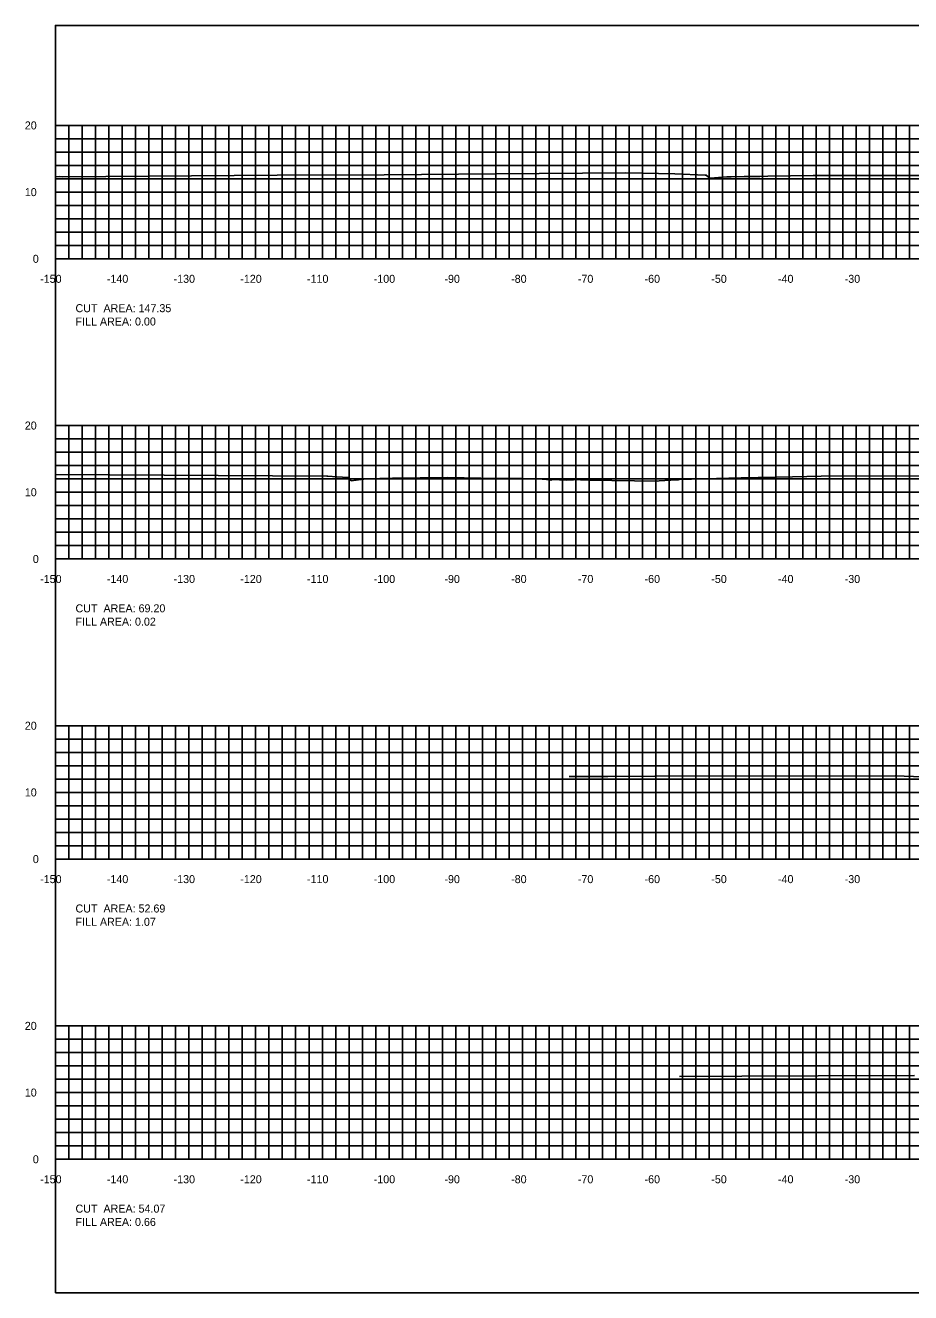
# Model space of a CAD drawing. Extents: x 1800674 to 1802785, y 250079 to 250269.
# Drawn here: x 1802136.5 to 1802269.2, y 250079.4 to 250269.4 of the extents above; entities that cross this region are included whole.
import ezdxf

# ---------------------------------------------------------------- set-up
doc = ezdxf.new("R2010")
doc.units = 0
for name, color, linetype in [('10', 7, 'Continuous'), ('31', 7, 'Continuous'), ('60', 7, 'Continuous'), ('ANNO-TXT', 7, 'Continuous'), ('Level 62', 7, 'Continuous'), ('M-ROADS', 7, 'Continuous')]:
    doc.layers.add(name, color=color, linetype=linetype)

msp = doc.modelspace()

# ---------------------------------------------------------------- linework, layer by layer
msp.add_lwpolyline([(1802141, 250079.43), (1802441, 250079.43), (1802441, 250269.43), (1802141, 250269.43)], close=True)
at = {"layer": '60'}
for p, q in [((1802140.94, 250254.43), (1802141, 250254.43)), ((1802141, 250234.43), (1802141, 250254.43)), ((1802140.94, 250244.43), (1802141, 250244.43)), ((1802140.94, 250234.43), (1802141, 250234.43)), ((1802141, 250234.43), (1802441, 250234.43)), ((1802141, 250234.37), (1802141, 250234.43)), ((1802151, 250234.37), (1802151, 250234.43)), ((1802161, 250234.37), (1802161, 250234.43)), ((1802171, 250234.37), (1802171, 250234.43)), ((1802181, 250234.37), (1802181, 250234.43)), ((1802191, 250234.37), (1802191, 250234.43)), ((1802201, 250234.37), (1802201, 250234.43)), ((1802211, 250234.37), (1802211, 250234.43)), ((1802221, 250234.37), (1802221, 250234.43)), ((1802231, 250234.37), (1802231, 250234.43)), ((1802241, 250234.37), (1802241, 250234.43)), ((1802251, 250234.37), (1802251, 250234.43)), ((1802261, 250234.37), (1802261, 250234.43)), ((1802140.94, 250209.43), (1802141, 250209.43)), ((1802141, 250189.43), (1802141, 250209.43)), ((1802140.94, 250199.43), (1802141, 250199.43)), ((1802140.94, 250189.43), (1802141, 250189.43)), ((1802141, 250189.43), (1802441, 250189.43)), ((1802141, 250189.37), (1802141, 250189.43)), ((1802151, 250189.37), (1802151, 250189.43)), ((1802161, 250189.37), (1802161, 250189.43)), ((1802171, 250189.37), (1802171, 250189.43)), ((1802181, 250189.37), (1802181, 250189.43)), ((1802191, 250189.37), (1802191, 250189.43)), ((1802201, 250189.37), (1802201, 250189.43)), ((1802211, 250189.37), (1802211, 250189.43)), ((1802221, 250189.37), (1802221, 250189.43)), ((1802231, 250189.37), (1802231, 250189.43)), ((1802241, 250189.37), (1802241, 250189.43)), ((1802251, 250189.37), (1802251, 250189.43)), ((1802261, 250189.37), (1802261, 250189.43)), ((1802140.94, 250164.43), (1802141, 250164.43)), ((1802141, 250144.43), (1802141, 250164.43)), ((1802140.94, 250154.43), (1802141, 250154.43)), ((1802140.94, 250144.43), (1802141, 250144.43)), ((1802141, 250144.43), (1802441, 250144.43)), ((1802141, 250144.37), (1802141, 250144.43)), ((1802151, 250144.37), (1802151, 250144.43)), ((1802161, 250144.37), (1802161, 250144.43)), ((1802171, 250144.37), (1802171, 250144.43)), ((1802181, 250144.37), (1802181, 250144.43)), ((1802191, 250144.37), (1802191, 250144.43)), ((1802201, 250144.37), (1802201, 250144.43)), ((1802211, 250144.37), (1802211, 250144.43)), ((1802221, 250144.37), (1802221, 250144.43)), ((1802231, 250144.37), (1802231, 250144.43)), ((1802241, 250144.37), (1802241, 250144.43)), ((1802251, 250144.37), (1802251, 250144.43)), ((1802261, 250144.37), (1802261, 250144.43)), ((1802140.94, 250119.43), (1802141, 250119.43)), ((1802141, 250099.43), (1802141, 250119.43)), ((1802140.94, 250109.43), (1802141, 250109.43)), ((1802140.94, 250099.43), (1802141, 250099.43)), ((1802141, 250099.43), (1802441, 250099.43)), ((1802141, 250099.37), (1802141, 250099.43)), ((1802151, 250099.37), (1802151, 250099.43)), ((1802161, 250099.37), (1802161, 250099.43)), ((1802171, 250099.37), (1802171, 250099.43)), ((1802181, 250099.37), (1802181, 250099.43)), ((1802191, 250099.37), (1802191, 250099.43)), ((1802201, 250099.37), (1802201, 250099.43)), ((1802211, 250099.37), (1802211, 250099.43)), ((1802221, 250099.37), (1802221, 250099.43)), ((1802231, 250099.37), (1802231, 250099.43)), ((1802241, 250099.37), (1802241, 250099.43)), ((1802251, 250099.37), (1802251, 250099.43)), ((1802261, 250099.37), (1802261, 250099.43))]:
    msp.add_line(p, q, dxfattribs=at)
at = {"layer": 'Level 62'}
for p, q in [((1802141, 250254.43), (1802441, 250254.43)), ((1802141, 250234.43), (1802141, 250254.43)), ((1802143, 250234.43), (1802143, 250254.43)), ((1802145, 250234.43), (1802145, 250254.43)), ((1802147, 250234.43), (1802147, 250254.43)), ((1802149, 250234.43), (1802149, 250254.43)), ((1802151, 250234.43), (1802151, 250254.43)), ((1802153, 250234.43), (1802153, 250254.43)), ((1802155, 250234.43), (1802155, 250254.43)), ((1802157, 250234.43), (1802157, 250254.43)), ((1802159, 250234.43), (1802159, 250254.43)), ((1802161, 250234.43), (1802161, 250254.43)), ((1802163, 250234.43), (1802163, 250254.43)), ((1802165, 250234.43), (1802165, 250254.43)), ((1802167, 250234.43), (1802167, 250254.43)), ((1802169, 250234.43), (1802169, 250254.43)), ((1802171, 250234.43), (1802171, 250254.43)), ((1802173, 250234.43), (1802173, 250254.43)), ((1802175, 250234.43), (1802175, 250254.43)), ((1802177, 250234.43), (1802177, 250254.43)), ((1802179, 250234.43), (1802179, 250254.43)), ((1802181, 250234.43), (1802181, 250254.43)), ((1802183, 250234.43), (1802183, 250254.43)), ((1802185, 250234.43), (1802185, 250254.43)), ((1802187, 250234.43), (1802187, 250254.43)), ((1802189, 250234.43), (1802189, 250254.43)), ((1802191, 250234.43), (1802191, 250254.43)), ((1802193, 250234.43), (1802193, 250254.43)), ((1802195, 250234.43), (1802195, 250254.43)), ((1802197, 250234.43), (1802197, 250254.43)), ((1802199, 250234.43), (1802199, 250254.43)), ((1802201, 250234.43), (1802201, 250254.43)), ((1802203, 250234.43), (1802203, 250254.43)), ((1802205, 250234.43), (1802205, 250254.43)), ((1802207, 250234.43), (1802207, 250254.43)), ((1802209, 250234.43), (1802209, 250254.43)), ((1802211, 250234.43), (1802211, 250254.43)), ((1802213, 250234.43), (1802213, 250254.43)), ((1802215, 250234.43), (1802215, 250254.43)), ((1802217, 250234.43), (1802217, 250254.43)), ((1802219, 250234.43), (1802219, 250254.43)), ((1802221, 250234.43), (1802221, 250254.43)), ((1802223, 250234.43), (1802223, 250254.43)), ((1802225, 250234.43), (1802225, 250254.43)), ((1802227, 250234.43), (1802227, 250254.43)), ((1802229, 250234.43), (1802229, 250254.43)), ((1802231, 250234.43), (1802231, 250254.43)), ((1802233, 250234.43), (1802233, 250254.43)), ((1802235, 250234.43), (1802235, 250254.43)), ((1802237, 250234.43), (1802237, 250254.43)), ((1802239, 250234.43), (1802239, 250254.43)), ((1802241, 250234.43), (1802241, 250254.43)), ((1802243, 250234.43), (1802243, 250254.43)), ((1802245, 250234.43), (1802245, 250254.43)), ((1802247, 250234.43), (1802247, 250254.43)), ((1802249, 250234.43), (1802249, 250254.43)), ((1802251, 250234.43), (1802251, 250254.43)), ((1802253, 250234.43), (1802253, 250254.43)), ((1802255, 250234.43), (1802255, 250254.43)), ((1802257, 250234.43), (1802257, 250254.43)), ((1802259, 250234.43), (1802259, 250254.43)), ((1802261, 250234.43), (1802261, 250254.43)), ((1802263, 250234.43), (1802263, 250254.43)), ((1802265, 250234.43), (1802265, 250254.43)), ((1802267, 250234.43), (1802267, 250254.43)), ((1802269, 250234.43), (1802269, 250254.43)), ((1802141, 250252.43), (1802441, 250252.43)), ((1802141, 250250.43), (1802441, 250250.43)), ((1802141, 250248.43), (1802441, 250248.43)), ((1802141, 250246.43), (1802441, 250246.43)), ((1802141, 250244.43), (1802441, 250244.43)), ((1802141, 250242.43), (1802441, 250242.43)), ((1802141, 250240.43), (1802441, 250240.43)), ((1802141, 250238.43), (1802441, 250238.43)), ((1802141, 250236.43), (1802441, 250236.43)), ((1802141, 250234.43), (1802441, 250234.43)), ((1802141, 250209.43), (1802441, 250209.43)), ((1802141, 250189.43), (1802141, 250209.43)), ((1802143, 250189.43), (1802143, 250209.43)), ((1802145, 250189.43), (1802145, 250209.43)), ((1802147, 250189.43), (1802147, 250209.43)), ((1802149, 250189.43), (1802149, 250209.43)), ((1802151, 250189.43), (1802151, 250209.43)), ((1802153, 250189.43), (1802153, 250209.43)), ((1802155, 250189.43), (1802155, 250209.43)), ((1802157, 250189.43), (1802157, 250209.43)), ((1802159, 250189.43), (1802159, 250209.43)), ((1802161, 250189.43), (1802161, 250209.43)), ((1802163, 250189.43), (1802163, 250209.43)), ((1802165, 250189.43), (1802165, 250209.43)), ((1802167, 250189.43), (1802167, 250209.43)), ((1802169, 250189.43), (1802169, 250209.43)), ((1802171, 250189.43), (1802171, 250209.43)), ((1802173, 250189.43), (1802173, 250209.43)), ((1802175, 250189.43), (1802175, 250209.43)), ((1802177, 250189.43), (1802177, 250209.43)), ((1802179, 250189.43), (1802179, 250209.43)), ((1802181, 250189.43), (1802181, 250209.43)), ((1802183, 250189.43), (1802183, 250209.43)), ((1802185, 250189.43), (1802185, 250209.43)), ((1802187, 250189.43), (1802187, 250209.43)), ((1802189, 250189.43), (1802189, 250209.43)), ((1802191, 250189.43), (1802191, 250209.43)), ((1802193, 250189.43), (1802193, 250209.43)), ((1802195, 250189.43), (1802195, 250209.43)), ((1802197, 250189.43), (1802197, 250209.43)), ((1802199, 250189.43), (1802199, 250209.43)), ((1802201, 250189.43), (1802201, 250209.43)), ((1802203, 250189.43), (1802203, 250209.43)), ((1802205, 250189.43), (1802205, 250209.43)), ((1802207, 250189.43), (1802207, 250209.43)), ((1802209, 250189.43), (1802209, 250209.43)), ((1802211, 250189.43), (1802211, 250209.43)), ((1802213, 250189.43), (1802213, 250209.43)), ((1802215, 250189.43), (1802215, 250209.43)), ((1802217, 250189.43), (1802217, 250209.43)), ((1802219, 250189.43), (1802219, 250209.43)), ((1802221, 250189.43), (1802221, 250209.43)), ((1802223, 250189.43), (1802223, 250209.43)), ((1802225, 250189.43), (1802225, 250209.43)), ((1802227, 250189.43), (1802227, 250209.43)), ((1802229, 250189.43), (1802229, 250209.43)), ((1802231, 250189.43), (1802231, 250209.43)), ((1802233, 250189.43), (1802233, 250209.43)), ((1802235, 250189.43), (1802235, 250209.43)), ((1802237, 250189.43), (1802237, 250209.43)), ((1802239, 250189.43), (1802239, 250209.43)), ((1802241, 250189.43), (1802241, 250209.43)), ((1802243, 250189.43), (1802243, 250209.43)), ((1802245, 250189.43), (1802245, 250209.43)), ((1802247, 250189.43), (1802247, 250209.43)), ((1802249, 250189.43), (1802249, 250209.43)), ((1802251, 250189.43), (1802251, 250209.43)), ((1802253, 250189.43), (1802253, 250209.43)), ((1802255, 250189.43), (1802255, 250209.43)), ((1802257, 250189.43), (1802257, 250209.43)), ((1802259, 250189.43), (1802259, 250209.43)), ((1802261, 250189.43), (1802261, 250209.43)), ((1802263, 250189.43), (1802263, 250209.43)), ((1802265, 250189.43), (1802265, 250209.43)), ((1802267, 250189.43), (1802267, 250209.43)), ((1802269, 250189.43), (1802269, 250209.43)), ((1802141, 250207.43), (1802441, 250207.43)), ((1802141, 250205.43), (1802441, 250205.43)), ((1802141, 250203.43), (1802441, 250203.43)), ((1802141, 250201.43), (1802441, 250201.43)), ((1802141, 250199.43), (1802441, 250199.43)), ((1802141, 250197.43), (1802441, 250197.43)), ((1802141, 250195.43), (1802441, 250195.43)), ((1802141, 250193.43), (1802441, 250193.43)), ((1802141, 250191.43), (1802441, 250191.43)), ((1802141, 250189.43), (1802441, 250189.43)), ((1802141, 250164.43), (1802441, 250164.43)), ((1802141, 250144.43), (1802141, 250164.43)), ((1802143, 250144.43), (1802143, 250164.43)), ((1802145, 250144.43), (1802145, 250164.43)), ((1802147, 250144.43), (1802147, 250164.43)), ((1802149, 250144.43), (1802149, 250164.43)), ((1802151, 250144.43), (1802151, 250164.43)), ((1802153, 250144.43), (1802153, 250164.43)), ((1802155, 250144.43), (1802155, 250164.43)), ((1802157, 250144.43), (1802157, 250164.43)), ((1802159, 250144.43), (1802159, 250164.43)), ((1802161, 250144.43), (1802161, 250164.43)), ((1802163, 250144.43), (1802163, 250164.43)), ((1802165, 250144.43), (1802165, 250164.43)), ((1802167, 250144.43), (1802167, 250164.43)), ((1802169, 250144.43), (1802169, 250164.43)), ((1802171, 250144.43), (1802171, 250164.43)), ((1802173, 250144.43), (1802173, 250164.43)), ((1802175, 250144.43), (1802175, 250164.43)), ((1802177, 250144.43), (1802177, 250164.43)), ((1802179, 250144.43), (1802179, 250164.43)), ((1802181, 250144.43), (1802181, 250164.43)), ((1802183, 250144.43), (1802183, 250164.43)), ((1802185, 250144.43), (1802185, 250164.43)), ((1802187, 250144.43), (1802187, 250164.43)), ((1802189, 250144.43), (1802189, 250164.43)), ((1802191, 250144.43), (1802191, 250164.43)), ((1802193, 250144.43), (1802193, 250164.43)), ((1802195, 250144.43), (1802195, 250164.43)), ((1802197, 250144.43), (1802197, 250164.43)), ((1802199, 250144.43), (1802199, 250164.43)), ((1802201, 250144.43), (1802201, 250164.43)), ((1802203, 250144.43), (1802203, 250164.43)), ((1802205, 250144.43), (1802205, 250164.43)), ((1802207, 250144.43), (1802207, 250164.43)), ((1802209, 250144.43), (1802209, 250164.43)), ((1802211, 250144.43), (1802211, 250164.43)), ((1802213, 250144.43), (1802213, 250164.43)), ((1802215, 250144.43), (1802215, 250164.43)), ((1802217, 250144.43), (1802217, 250164.43)), ((1802219, 250144.43), (1802219, 250164.43)), ((1802221, 250144.43), (1802221, 250164.43)), ((1802223, 250144.43), (1802223, 250164.43)), ((1802225, 250144.43), (1802225, 250164.43)), ((1802227, 250144.43), (1802227, 250164.43)), ((1802229, 250144.43), (1802229, 250164.43)), ((1802231, 250144.43), (1802231, 250164.43)), ((1802233, 250144.43), (1802233, 250164.43)), ((1802235, 250144.43), (1802235, 250164.43)), ((1802237, 250144.43), (1802237, 250164.43)), ((1802239, 250144.43), (1802239, 250164.43)), ((1802241, 250144.43), (1802241, 250164.43)), ((1802243, 250144.43), (1802243, 250164.43)), ((1802245, 250144.43), (1802245, 250164.43)), ((1802247, 250144.43), (1802247, 250164.43)), ((1802249, 250144.43), (1802249, 250164.43)), ((1802251, 250144.43), (1802251, 250164.43)), ((1802253, 250144.43), (1802253, 250164.43)), ((1802255, 250144.43), (1802255, 250164.43)), ((1802257, 250144.43), (1802257, 250164.43)), ((1802259, 250144.43), (1802259, 250164.43)), ((1802261, 250144.43), (1802261, 250164.43)), ((1802263, 250144.43), (1802263, 250164.43)), ((1802265, 250144.43), (1802265, 250164.43)), ((1802267, 250144.43), (1802267, 250164.43)), ((1802269, 250144.43), (1802269, 250164.43)), ((1802141, 250162.43), (1802441, 250162.43)), ((1802141, 250160.43), (1802441, 250160.43)), ((1802141, 250158.43), (1802441, 250158.43)), ((1802141, 250156.43), (1802441, 250156.43)), ((1802141, 250154.43), (1802441, 250154.43)), ((1802141, 250152.43), (1802441, 250152.43)), ((1802141, 250150.43), (1802441, 250150.43)), ((1802141, 250148.43), (1802441, 250148.43)), ((1802141, 250146.43), (1802441, 250146.43)), ((1802141, 250144.43), (1802441, 250144.43)), ((1802141, 250119.43), (1802441, 250119.43)), ((1802141, 250099.43), (1802141, 250119.43)), ((1802143, 250099.43), (1802143, 250119.43)), ((1802145, 250099.43), (1802145, 250119.43)), ((1802147, 250099.43), (1802147, 250119.43)), ((1802149, 250099.43), (1802149, 250119.43)), ((1802151, 250099.43), (1802151, 250119.43)), ((1802153, 250099.43), (1802153, 250119.43)), ((1802155, 250099.43), (1802155, 250119.43)), ((1802157, 250099.43), (1802157, 250119.43)), ((1802159, 250099.43), (1802159, 250119.43)), ((1802161, 250099.43), (1802161, 250119.43)), ((1802163, 250099.43), (1802163, 250119.43)), ((1802165, 250099.43), (1802165, 250119.43)), ((1802167, 250099.43), (1802167, 250119.43)), ((1802169, 250099.43), (1802169, 250119.43)), ((1802171, 250099.43), (1802171, 250119.43)), ((1802173, 250099.43), (1802173, 250119.43)), ((1802175, 250099.43), (1802175, 250119.43)), ((1802177, 250099.43), (1802177, 250119.43)), ((1802179, 250099.43), (1802179, 250119.43)), ((1802181, 250099.43), (1802181, 250119.43)), ((1802183, 250099.43), (1802183, 250119.43)), ((1802185, 250099.43), (1802185, 250119.43)), ((1802187, 250099.43), (1802187, 250119.43)), ((1802189, 250099.43), (1802189, 250119.43)), ((1802191, 250099.43), (1802191, 250119.43)), ((1802193, 250099.43), (1802193, 250119.43)), ((1802195, 250099.43), (1802195, 250119.43)), ((1802197, 250099.43), (1802197, 250119.43)), ((1802199, 250099.43), (1802199, 250119.43)), ((1802201, 250099.43), (1802201, 250119.43)), ((1802203, 250099.43), (1802203, 250119.43)), ((1802205, 250099.43), (1802205, 250119.43)), ((1802207, 250099.43), (1802207, 250119.43)), ((1802209, 250099.43), (1802209, 250119.43)), ((1802211, 250099.43), (1802211, 250119.43)), ((1802213, 250099.43), (1802213, 250119.43)), ((1802215, 250099.43), (1802215, 250119.43)), ((1802217, 250099.43), (1802217, 250119.43)), ((1802219, 250099.43), (1802219, 250119.43)), ((1802221, 250099.43), (1802221, 250119.43)), ((1802223, 250099.43), (1802223, 250119.43)), ((1802225, 250099.43), (1802225, 250119.43)), ((1802227, 250099.43), (1802227, 250119.43)), ((1802229, 250099.43), (1802229, 250119.43)), ((1802231, 250099.43), (1802231, 250119.43)), ((1802233, 250099.43), (1802233, 250119.43)), ((1802235, 250099.43), (1802235, 250119.43)), ((1802237, 250099.43), (1802237, 250119.43)), ((1802239, 250099.43), (1802239, 250119.43)), ((1802241, 250099.43), (1802241, 250119.43)), ((1802243, 250099.43), (1802243, 250119.43)), ((1802245, 250099.43), (1802245, 250119.43)), ((1802247, 250099.43), (1802247, 250119.43)), ((1802249, 250099.43), (1802249, 250119.43)), ((1802251, 250099.43), (1802251, 250119.43)), ((1802253, 250099.43), (1802253, 250119.43)), ((1802255, 250099.43), (1802255, 250119.43)), ((1802257, 250099.43), (1802257, 250119.43)), ((1802259, 250099.43), (1802259, 250119.43)), ((1802261, 250099.43), (1802261, 250119.43)), ((1802263, 250099.43), (1802263, 250119.43)), ((1802265, 250099.43), (1802265, 250119.43)), ((1802267, 250099.43), (1802267, 250119.43)), ((1802269, 250099.43), (1802269, 250119.43)), ((1802141, 250117.43), (1802441, 250117.43)), ((1802141, 250115.43), (1802441, 250115.43)), ((1802141, 250113.43), (1802441, 250113.43)), ((1802141, 250111.43), (1802441, 250111.43)), ((1802141, 250109.43), (1802441, 250109.43)), ((1802141, 250107.43), (1802441, 250107.43)), ((1802141, 250105.43), (1802441, 250105.43)), ((1802141, 250103.43), (1802441, 250103.43)), ((1802141, 250101.43), (1802441, 250101.43)), ((1802141, 250099.43), (1802441, 250099.43))]:
    msp.add_line(p, q, dxfattribs=at)
at = {"layer": 'M-ROADS'}
for points in [[(1802141, 250246.73), (1802141.54, 250246.75), (1802142.08, 250246.74), (1802174.22, 250246.96), (1802190.26, 250247.02), (1802207.02, 250247.17), (1802226.5, 250247.32), (1802233.82, 250247.15), (1802238.39, 250246.98), (1802238.5, 250246.97), (1802238.51, 250246.96), (1802239.07, 250246.52), (1802239.12, 250246.53), (1802241.63, 250246.73), (1802241.67, 250246.73), (1802242.11, 250246.74), (1802242.26, 250246.74), (1802244.23, 250246.76), (1802246.58, 250246.78), (1802247.8, 250246.8), (1802254.59, 250246.93), (1802265.15, 250246.92), (1802270.89, 250246.9)], [(1802141, 250202.07), (1802181.66, 250201.83), (1802181.81, 250201.82), (1802183.15, 250201.72), (1802184.89, 250201.62), (1802185.08, 250201.43), (1802185.33, 250201.16), (1802186.82, 250201.34), (1802187.68, 250201.45), (1802191.54, 250201.56), (1802199.8, 250201.65), (1802207.2, 250201.47), (1802210.9, 250201.51), (1802213.31, 250201.46), (1802214.6, 250201.32), (1802215.26, 250201.26), (1802215.51, 250201.32), (1802215.91, 250201.32), (1802216.55, 250201.31), (1802217.61, 250201.24), (1802219.68, 250201.33), (1802219.72, 250201.3), (1802219.76, 250201.29), (1802221, 250201.26), (1802231.2, 250201.08), (1802231.5, 250201.12), (1802234.11, 250201.31), (1802234.36, 250201.29), (1802234.5, 250201.34), (1802234.51, 250201.34), (1802243.79, 250201.6), (1802251.47, 250201.73), (1802255.78, 250201.86), (1802275.21, 250201.91)], [(1802217.98, 250156.8), (1802223.77, 250156.82), (1802230.85, 250156.87), (1802266.87, 250156.92), (1802276.48, 250156.58)], [(1802234.52, 250111.84), (1802243.89, 250111.87), (1802255.34, 250111.96), (1802269.75, 250111.98)]]:
    msp.add_lwpolyline(points, dxfattribs=at)

# ---------------------------------------------------------------- texts
at = {"layer": '10'}
for s, p in [('-150', (1802138.7, 250230.83)), ('-140', (1802148.7, 250230.83)), ('-130', (1802158.7, 250230.83)), ('-120', (1802168.7, 250230.83)), ('-110', (1802178.7, 250230.83)), ('-100', (1802188.7, 250230.83)), ('-90', (1802199.3, 250230.83)), ('-80', (1802209.3, 250230.83)), ('-70', (1802219.3, 250230.83)), ('-60', (1802229.3, 250230.83)), ('-50', (1802239.3, 250230.83)), ('-40', (1802249.3, 250230.83)), ('-30', (1802259.3, 250230.83)), ('-150', (1802138.7, 250185.83)), ('-140', (1802148.7, 250185.83)), ('-130', (1802158.7, 250185.83)), ('-120', (1802168.7, 250185.83)), ('-110', (1802178.7, 250185.83)), ('-100', (1802188.7, 250185.83)), ('-90', (1802199.3, 250185.83)), ('-80', (1802209.3, 250185.83)), ('-70', (1802219.3, 250185.83)), ('-60', (1802229.3, 250185.83)), ('-50', (1802239.3, 250185.83)), ('-40', (1802249.3, 250185.83)), ('-30', (1802259.3, 250185.83)), ('-150', (1802138.7, 250140.83)), ('-140', (1802148.7, 250140.83)), ('-130', (1802158.7, 250140.83)), ('-120', (1802168.7, 250140.83)), ('-110', (1802178.7, 250140.83)), ('-100', (1802188.7, 250140.83)), ('-90', (1802199.3, 250140.83)), ('-80', (1802209.3, 250140.83)), ('-70', (1802219.3, 250140.83)), ('-60', (1802229.3, 250140.83)), ('-50', (1802239.3, 250140.83)), ('-40', (1802249.3, 250140.83)), ('-30', (1802259.3, 250140.83)), ('-150', (1802138.7, 250095.83)), ('-140', (1802148.7, 250095.83)), ('-130', (1802158.7, 250095.83)), ('-120', (1802168.7, 250095.83)), ('-110', (1802178.7, 250095.83)), ('-100', (1802188.7, 250095.83)), ('-90', (1802199.3, 250095.83)), ('-80', (1802209.3, 250095.83)), ('-70', (1802219.3, 250095.83)), ('-60', (1802229.3, 250095.83)), ('-50', (1802239.3, 250095.83)), ('-40', (1802249.3, 250095.83)), ('-30', (1802259.3, 250095.83))]:
    msp.add_text(s, height=1.2, dxfattribs=at).set_placement(p)
at = {"layer": '31'}
for s, p in [('20', (1802136.4, 250253.83)), ('10', (1802136.4, 250243.83)), ('0', (1802137.6, 250233.83)), ('20', (1802136.4, 250208.83)), ('10', (1802136.4, 250198.83)), ('0', (1802137.6, 250188.83)), ('20', (1802136.4, 250163.83)), ('10', (1802136.4, 250153.83)), ('0', (1802137.6, 250143.83)), ('20', (1802136.4, 250118.83)), ('10', (1802136.4, 250108.83)), ('0', (1802137.6, 250098.83))]:
    msp.add_text(s, height=1.2, dxfattribs=at).set_placement(p)
at = {"layer": '60'}
for p in [(1802141, 250234.43), (1802141, 250189.43), (1802141, 250144.43), (1802141, 250099.43)]:
    msp.add_text('-', height=0.0001, dxfattribs=at).set_placement(p)
at = {"layer": 'ANNO-TXT'}
for s, p in [('CUT  AREA: 147.35', (1802144, 250226.43)), ('FILL AREA: 0.00', (1802144, 250224.43)), ('CUT  AREA: 69.20', (1802144, 250181.43)), ('FILL AREA: 0.02', (1802144, 250179.43)), ('CUT  AREA: 52.69', (1802144, 250136.43)), ('FILL AREA: 1.07', (1802144, 250134.43)), ('CUT  AREA: 54.07', (1802144, 250091.43)), ('FILL AREA: 0.66', (1802144, 250089.43))]:
    msp.add_text(s, height=1.2, dxfattribs=at).set_placement(p)

doc.saveas('drawing.dxf')
